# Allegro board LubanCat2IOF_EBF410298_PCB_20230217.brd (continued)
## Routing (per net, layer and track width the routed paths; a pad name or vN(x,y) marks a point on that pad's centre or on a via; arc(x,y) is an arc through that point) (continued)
MIPI_DSI_TX0_D3N: length 111.2
  TOP w0.114: J38.224 72.35,71.42 arc(72.36,71.49) 72.41,71.56 72.42,71.57 arc(72.46,71.64) 72.48,71.71 72.48,74.75 arc(72.67,75.21) 73.13,75.4 96.93,75.4 v1(97.26,75.73) ; J23.30 152.2,78.93 arc(152.27,78.91) 152.34,78.87 152.35,78.85 arc(152.42,78.81) 152.49,78.8 155.18,78.8 arc(155.39,78.84) 155.56,78.95 v1(155.73,79.12)
  ART03 w0.102: v1(97.26,75.73) 97.1,75.57 arc(96.94,75.46) 96.74,75.42 arc(96.35,75.26) 96.18,74.86 96.18,74.71 arc(96.38,74.23) 96.85,74.04 98.01,74.04 arc(98.21,74.08) 98.37,74.19 99.3,75.12 arc(99.46,75.22) 99.64,75.26 arc(100.99,75.53) 102.14,76.29 102.95,77.1 arc(103.27,77.32) 103.64,77.39 146.07,77.39 arc(146.5,77.3) 146.86,77.06 arc(146.94,76.95) 146.96,76.81 146.96,72.71 arc(147,72.52) 147.11,72.35 147.13,72.33 arc(147.3,72.22) 147.49,72.18 150.75,72.18 arc(150.83,72.17) 150.9,72.12 151.75,71.27 arc(151.92,71.15) 152.11,71.12 155.88,71.12 arc(156.49,71.37) 156.74,71.98 156.74,78.31 arc(156.6,78.67) 156.24,78.81 arc(156.05,78.85) 155.89,78.96 v1(155.73,79.12)
MIPI_DSI_TX0_D3P: length 111.2
  TOP w0.114: J38.226 72.85,71.5 72.72,71.63 72.72,74.75 arc(72.84,75.04) 73.13,75.16 73.98,75.16 arc(74.1,75.11) 74.15,74.99 arc(74.19,74.87) 74.31,74.82 74.43,74.82 arc(74.55,74.87) 74.6,74.99 arc(74.65,75.11) 74.77,75.16 74.89,75.16 arc(75.01,75.11) 75.06,74.99 arc(75.11,74.87) 75.23,74.82 75.35,74.82 arc(75.47,74.87) 75.52,74.99 arc(75.57,75.11) 75.69,75.16 75.81,75.16 arc(75.93,75.11) 75.97,74.99 arc(76.04,74.84) 76.19,74.77 76.21,74.77 arc(76.37,74.84) 76.43,74.99 arc(76.48,75.11) 76.6,75.16 77.74,75.16 arc(77.87,75.1) 77.93,74.97 arc(77.99,74.83) 78.12,74.77 78.19,74.77 arc(78.33,74.83) 78.39,74.97 arc(78.44,75.1) 78.58,75.16 78.65,75.16 arc(78.79,75.1) 78.84,74.97 arc(78.9,74.83) 79.04,74.77 79.11,74.77 arc(79.24,74.83) 79.3,74.97 arc(79.36,75.1) 79.5,75.16 96.93,75.16 v1(97.26,74.84) ; J23.29 152.28,78.42 152.35,78.5 arc(152.42,78.54) 152.49,78.55 155.18,78.55 arc(155.39,78.51) 155.56,78.4 v1(155.73,78.23)
  ART03 w0.102: v1(155.73,78.23) 155.89,78.39 arc(156.05,78.5) 156.24,78.54 156.24,78.54 arc(156.4,78.47) 156.46,78.31 156.46,71.98 arc(156.29,71.57) 155.88,71.4 152.11,71.4 arc(152.03,71.41) 151.95,71.46 151.09,72.32 arc(150.94,72.43) 150.75,72.46 147.49,72.46 arc(147.4,72.48) 147.33,72.53 147.31,72.55 arc(147.26,72.62) 147.24,72.71 147.24,76.81 arc(147.2,77.05) 147.06,77.26 arc(146.6,77.56) 146.07,77.67 103.64,77.67 arc(103.16,77.57) 102.76,77.3 101.95,76.49 arc(100.89,75.78) 99.64,75.54 arc(99.35,75.48) 99.1,75.31 98.17,74.38 arc(98.1,74.33) 98.01,74.32 96.85,74.32 arc(96.58,74.43) 96.46,74.71 96.46,74.86 arc(96.54,75.06) 96.74,75.14 arc(96.94,75.1) 97.1,75 v1(97.26,74.84)
MIPI_DSI_TX1_CLKN: length 96.1
  TOP w0.114: J38.207 67.6,61.38 arc(67.61,61.31) 67.66,61.24 67.67,61.23 arc(67.71,61.16) 67.73,61.09 67.73,60.62 arc(67.88,59.88) 68.3,59.24 71.49,56.06 arc(71.9,55.78) 72.38,55.69 75.6,55.69 arc(75.8,55.65) 75.97,55.53 v1(76.14,55.36) ; v1(118.57,56.53) 118.74,56.36 arc(118.91,56.25) 119.11,56.21 129.08,56.21 arc(130.26,55.97) 131.25,55.31 132.87,53.69 arc(133.56,53.23) 134.38,53.06 150.47,53.06 arc(150.54,53.08) 150.61,53.12 150.62,53.14 arc(150.69,53.18) 150.76,53.19 J26.24
  BOTTOM w0.114: v1(76.14,55.36) 76.3,55.52 arc(76.46,55.62) 76.64,55.66 77.97,55.66 arc(78.19,55.7) 78.37,55.83 79.07,56.53 arc(80.24,57.31) 81.63,57.59 85.85,57.59 arc(86.22,57.74) 86.38,58.11 86.38,58.52 arc(86.66,58.81) 86.95,58.52 86.95,58.11 arc(87.1,57.74) 87.48,57.59 119.85,57.59 arc(120.01,57.52) 120.08,57.36 120.08,56.43 arc(120.01,56.27) 119.85,56.21 119.11,56.21 arc(118.91,56.25) 118.74,56.36 v1(118.57,56.53)
MIPI_DSI_TX1_CLKP: length 96.5
  TOP w0.114: v1(76.14,56.25) 75.97,56.08 arc(75.8,55.97) 75.6,55.93 72.38,55.93 arc(71.99,56.01) 71.66,56.23 68.47,59.41 arc(68.1,59.97) 67.97,60.62 67.97,61.09 arc(67.99,61.16) 68.03,61.23 68.04,61.24 arc(68.09,61.31) 68.1,61.38 J38.209 ; J26.23 150.76,52.69 arc(150.69,52.71) 150.62,52.75 150.61,52.76 arc(150.54,52.81) 150.47,52.82 134.38,52.82 arc(133.47,53) 132.7,53.52 131.08,55.14 arc(130.16,55.75) 129.08,55.97 119.11,55.97 arc(118.91,55.92) 118.74,55.81 v1(118.57,55.64)
  BOTTOM w0.114: v1(76.14,56.25) 76.33,56.07 arc(76.51,55.95) 76.73,55.9 77.97,55.9 arc(78.09,55.93) 78.2,56 78.9,56.7 arc(80.15,57.53) 81.63,57.83 85.85,57.83 arc(86.05,57.91) 86.14,58.11 86.14,58.52 arc(86.66,59.05) 87.19,58.52 87.19,58.11 arc(87.27,57.91) 87.48,57.83 119.85,57.83 arc(120.18,57.69) 120.32,57.36 120.32,56.43 arc(120.18,56.1) 119.85,55.97 119.11,55.97 arc(118.91,55.92) 118.74,55.81 v1(118.57,55.64)
MIPI_DSI_TX1_D0N: length 96.8
  TOP w0.114: v1(114.22,54.35) 114.39,54.52 arc(114.5,54.69) 114.54,54.9 114.54,54.93 arc(114.74,55.92) 115.3,56.76 arc(116.37,57.48) 117.65,57.73 129.29,57.73 arc(130.69,57.45) 131.87,56.66 132.84,55.69 arc(134.09,54.86) 135.57,54.56 150.47,54.56 arc(150.54,54.58) 150.61,54.62 150.62,54.64 arc(150.69,54.68) 150.76,54.69 J26.27 ; v1(76.14,52.79) 75.97,52.96 arc(75.8,53.07) 75.6,53.11 73.9,53.11 arc(71.97,53.5) 70.34,54.59 65.9,59.02 arc(65.4,59.77) 65.23,60.65 65.23,61.09 arc(65.21,61.16) 65.17,61.23 65.16,61.24 arc(65.11,61.31) 65.1,61.38 J38.197
  BOTTOM w0.114: v1(114.22,54.35) 114.39,54.52 arc(114.5,54.69) 114.54,54.9 arc(114.34,55.39) 113.84,55.6 81.95,55.6 arc(81.01,55.41) 80.22,54.88 78.83,53.49 arc(78.31,53.14) 77.69,53.02 76.52,53.02 arc(76.38,52.99) 76.27,52.91 v1(76.14,52.79)
MIPI_DSI_TX1_D0P: length 97.5
  TOP w0.114: v1(76.14,53.68) 75.97,53.51 arc(75.8,53.4) 75.6,53.36 73.9,53.36 arc(72.06,53.72) 70.51,54.76 66.07,59.2 arc(65.63,59.86) 65.47,60.65 65.47,61.09 arc(65.49,61.16) 65.53,61.23 65.54,61.24 arc(65.59,61.31) 65.6,61.38 J38.199 ; J26.26 150.76,54.19 arc(150.69,54.21) 150.62,54.25 150.61,54.26 arc(150.54,54.31) 150.47,54.32 150.17,54.32 arc(150.09,54.29) 150.06,54.21 arc(150.03,54.13) 149.95,54.1 149.72,54.1 arc(149.64,54.13) 149.6,54.21 arc(149.57,54.29) 149.49,54.32 149.25,54.32 arc(149.19,54.3) 149.17,54.24 arc(149.14,54.18) 149.09,54.16 148.68,54.16 arc(148.62,54.18) 148.6,54.24 arc(148.57,54.3) 148.51,54.32 148.11,54.32 arc(148.05,54.3) 148.03,54.24 arc(148,54.18) 147.94,54.16 147.54,54.16 arc(147.48,54.18) 147.45,54.24 arc(147.43,54.3) 147.37,54.32 146.96,54.32 arc(146.91,54.3) 146.88,54.24 arc(146.86,54.18) 146.8,54.16 146.39,54.16 arc(146.33,54.18) 146.31,54.24 arc(146.29,54.3) 146.23,54.32 145.82,54.32 arc(145.76,54.3) 145.74,54.24 arc(145.71,54.18) 145.66,54.16 145.25,54.16 arc(145.19,54.18) 145.17,54.24 arc(145.14,54.3) 145.08,54.32 135.57,54.32 arc(134,54.63) 132.67,55.52 131.7,56.49 arc(130.59,57.23) 129.29,57.49 117.65,57.49 arc(116.47,57.25) 115.47,56.59 arc(114.96,55.83) 114.78,54.93 114.78,54.9 arc(114.82,54.69) 114.94,54.52 v1(115.11,54.35)
  BOTTOM w0.114: v1(76.14,53.68) 76.4,53.43 arc(76.58,53.3) 76.8,53.26 77.69,53.26 arc(78.21,53.36) 78.66,53.66 80.04,55.05 arc(80.92,55.63) 81.95,55.84 113.84,55.84 arc(114.51,55.56) 114.78,54.9 arc(114.82,54.69) 114.94,54.52 v1(115.11,54.35)
MIPI_DSI_TX1_D1N: length 96.1
  TOP w0.114: v1(74.52,54.09) 74.35,54.26 arc(74.18,54.38) 73.97,54.42 72.5,54.42 arc(71.79,54.56) 71.19,54.96 66.61,59.54 arc(66.33,59.96) 66.23,60.46 66.23,61.09 arc(66.21,61.16) 66.17,61.23 66.16,61.24 arc(66.11,61.31) 66.1,61.38 J38.201 ; J26.21 150.76,51.69 arc(150.69,51.68) 150.62,51.64 150.61,51.62 arc(150.54,51.58) 150.47,51.56 149.83,51.56 arc(149.76,51.59) 149.73,51.66 arc(149.7,51.73) 149.63,51.76 149.26,51.76 arc(149.19,51.73) 149.16,51.66 arc(149.13,51.59) 149.06,51.56 148.69,51.56 arc(148.62,51.59) 148.59,51.66 arc(148.56,51.73) 148.49,51.76 148.12,51.76 arc(148.05,51.73) 148.02,51.66 arc(147.99,51.59) 147.92,51.56 133.51,51.56 arc(132.92,51.68) 132.43,52.01 129.97,54.47 arc(129.48,54.79) 128.91,54.91 116.77,54.91 arc(116.57,54.95) 116.4,55.06 v1(116.23,55.23)
  BOTTOM w0.114: v1(74.52,54.09) 74.66,54.23 arc(74.79,54.32) 74.95,54.35 78.09,54.35 arc(78.31,54.4) 78.49,54.52 79.66,55.69 arc(80.63,56.33) 81.77,56.56 116.83,56.56 arc(117.02,56.48) 117.11,56.28 117.11,55.11 arc(117.05,54.97) 116.9,54.91 116.77,54.91 arc(116.57,54.95) 116.4,55.06 v1(116.23,55.23)
MIPI_DSI_TX1_D1P: length 96.1
  TOP w0.114: v1(116.23,54.34) 116.4,54.51 arc(116.57,54.63) 116.77,54.67 128.91,54.67 arc(129.39,54.57) 129.8,54.3 132.26,51.84 arc(132.83,51.46) 133.51,51.32 150.47,51.32 arc(150.54,51.31) 150.61,51.26 150.62,51.25 arc(150.69,51.21) 150.76,51.19 J26.20 ; v1(74.52,54.98) 74.35,54.81 arc(74.18,54.7) 73.97,54.66 72.5,54.66 arc(71.88,54.78) 71.36,55.13 66.78,59.71 arc(66.55,60.05) 66.47,60.46 66.47,61.09 arc(66.49,61.16) 66.53,61.23 66.54,61.24 arc(66.59,61.31) 66.6,61.38 J38.203
  BOTTOM w0.114: v1(116.23,54.34) 116.4,54.51 arc(116.57,54.63) 116.77,54.67 116.9,54.67 arc(117.22,54.8) 117.35,55.11 117.35,56.28 arc(117.2,56.65) 116.83,56.8 81.77,56.8 arc(80.54,56.56) 79.49,55.86 78.32,54.69 arc(78.22,54.62) 78.09,54.59 75.14,54.59 arc(74.92,54.64) 74.74,54.76 v1(74.52,54.98)
MIPI_DSI_TX1_D2N: length 96.7
  TOP w0.114: v1(74.52,56.5) 74.29,56.73 arc(74.11,56.86) 73.89,56.9 72.63,56.9 arc(72.12,57) 71.69,57.29 69.69,59.29 arc(69.35,59.8) 69.23,60.39 69.23,61.09 arc(69.21,61.16) 69.17,61.23 69.16,61.24 arc(69.11,61.31) 69.1,61.38 J38.213 ; J26.18 150.76,50.19 arc(150.69,50.18) 150.62,50.14 150.61,50.12 arc(150.54,50.08) 150.47,50.06 150.23,50.06 arc(150.18,50.08) 150.17,50.12 arc(150.15,50.17) 150.1,50.19 149.77,50.19 arc(149.73,50.17) 149.71,50.12 arc(149.69,50.08) 149.65,50.06 133.53,50.06 arc(132.35,50.3) 131.35,50.96 129.42,52.89 arc(128.65,53.41) 127.74,53.59 120.41,53.59 arc(120.2,53.63) 120.03,53.74 v1(119.86,53.92)
  BOTTOM w0.114: v1(119.86,53.92) 120.08,53.7 arc(120.2,53.62) 120.34,53.59 120.49,53.59 arc(120.83,53.73) 120.97,54.07 120.97,57.64 arc(120.68,58.32) 120,58.61 89.28,58.61 arc(88.88,58.77) 88.71,59.18 88.71,59.56 arc(88.64,59.72) 88.48,59.79 85.81,59.79 arc(85.65,59.72) 85.59,59.56 85.59,59.22 arc(85.54,59) 85.41,58.8 arc(85.19,58.66) 84.94,58.61 81.71,58.61 arc(79.74,58.21) 78.07,57.1 arc(77.88,56.97) 77.66,56.93 75.18,56.93 arc(74.96,56.89) 74.78,56.76 v1(74.52,56.5)
MIPI_DSI_TX1_D2P: length 96.8
  TOP w0.114: v1(74.52,57.39) 74.38,57.26 arc(74.25,57.17) 74.09,57.14 72.63,57.14 arc(72.21,57.22) 71.86,57.46 69.86,59.46 arc(69.57,59.89) 69.47,60.39 69.47,61.09 arc(69.49,61.16) 69.53,61.23 69.54,61.24 arc(69.59,61.31) 69.6,61.38 J38.215 ; v1(119.86,53.02) 120.03,53.19 arc(120.2,53.31) 120.41,53.35 127.74,53.35 arc(128.56,53.19) 129.25,52.72 131.18,50.79 arc(132.26,50.07) 133.53,49.82 150.47,49.82 arc(150.54,49.81) 150.61,49.76 150.62,49.75 arc(150.69,49.71) 150.76,49.69 J26.17
  BOTTOM w0.114: v1(119.86,53.02) 120.05,53.21 arc(120.2,53.31) 120.39,53.35 120.49,53.35 arc(121,53.56) 121.21,54.07 121.21,57.64 arc(120.85,58.49) 120,58.85 89.28,58.85 arc(89.05,58.94) 88.95,59.18 88.95,59.56 arc(88.81,59.89) 88.48,60.03 85.81,60.03 arc(85.48,59.89) 85.34,59.56 85.34,59.22 arc(85.32,59.09) 85.24,58.97 arc(85.1,58.88) 84.94,58.85 81.71,58.85 arc(79.65,58.44) 77.9,57.27 arc(77.79,57.2) 77.66,57.17 74.89,57.17 arc(74.75,57.2) 74.64,57.28 v1(74.52,57.39)
MIPI_DSI_TX1_D3N: length 95.8
  TOP w0.114: v1(76.14,57.77) 75.86,58.06 arc(75.67,58.18) 75.45,58.23 72.78,58.23 arc(72.05,58.37) 71.43,58.78 70.58,59.63 arc(70.32,60.02) 70.23,60.48 70.23,61.09 arc(70.21,61.16) 70.17,61.23 70.16,61.24 arc(70.11,61.31) 70.1,61.38 J38.217 ; J26.30 150.76,56.19 arc(150.69,56.18) 150.62,56.14 150.61,56.12 arc(150.54,56.08) 150.47,56.06 135.29,56.06 arc(134.31,56.26) 133.48,56.81 132.72,57.58 arc(131.23,58.57) 129.47,58.92 118.47,58.92 arc(118.38,58.94) 118.31,58.99 117.66,59.64 arc(117.61,59.71) 117.6,59.8 117.6,60.2 arc(117.66,60.54) 117.85,60.82 v1(117.86,60.83)
  BOTTOM w0.114: v1(76.14,57.77) 76.32,57.95 arc(76.51,58.08) 76.72,58.12 77.27,58.12 arc(77.48,58.16) 77.67,58.29 arc(79.12,59.25) 80.82,59.59 82.09,59.59 arc(82.47,59.75) 82.62,60.12 82.62,60.36 arc(82.7,60.56) 82.9,60.64 82.91,60.64 arc(83.11,60.55) 83.19,60.35 83.19,60.12 arc(83.35,59.75) 83.72,59.59 83.96,59.59 arc(84.14,59.63) 84.29,59.73 arc(84.42,59.92) 84.47,60.15 84.47,61.48 arc(84.53,61.63) 84.68,61.69 84.92,61.69 arc(85.13,61.61) 85.21,61.41 85.21,61.28 arc(85.37,60.91) 85.74,60.75 85.79,60.75 arc(86.13,60.89) 86.26,61.22 86.26,61.41 arc(86.55,61.69) 86.84,61.41 86.84,61.28 arc(86.99,60.91) 87.36,60.75 87.42,60.75 arc(87.75,60.89) 87.89,61.22 87.89,61.41 arc(87.97,61.61) 88.18,61.69 89.55,61.69 arc(89.71,61.63) 89.78,61.46 89.78,60.08 arc(89.92,59.73) 90.26,59.59 116.88,59.59 arc(117.1,59.63) 117.29,59.76 117.44,59.91 arc(117.56,60.09) 117.6,60.29 arc(117.65,60.54) 117.79,60.76 v1(117.86,60.83)
MIPI_DSI_TX1_D3P: length 96
  TOP w0.114: J38.219 70.6,61.38 arc(70.59,61.31) 70.54,61.24 70.53,61.23 arc(70.49,61.16) 70.47,61.09 70.47,60.48 arc(70.54,60.11) 70.75,59.8 71.6,58.96 arc(72.14,58.59) 72.78,58.47 75.82,58.47 arc(75.94,58.49) 76.04,58.56 v1(76.14,58.66) ; J26.29 150.76,55.69 arc(150.69,55.71) 150.62,55.75 150.61,55.76 arc(150.54,55.81) 150.47,55.82 150.16,55.82 arc(150.08,55.79) 150.05,55.71 arc(150.01,55.63) 149.93,55.6 149.7,55.6 arc(149.62,55.63) 149.59,55.71 arc(149.55,55.79) 149.48,55.82 149.23,55.82 arc(149.15,55.79) 149.12,55.71 arc(149.09,55.63) 149.01,55.6 148.66,55.6 arc(148.58,55.63) 148.55,55.71 arc(148.52,55.79) 148.44,55.82 135.29,55.82 arc(134.22,56.03) 133.31,56.64 132.55,57.41 arc(131.14,58.35) 129.47,58.68 118.47,58.68 arc(118.29,58.72) 118.14,58.82 117.49,59.47 arc(117.39,59.62) 117.35,59.8 117.35,60.2 arc(117.31,60.42) 117.19,60.61 v1(116.97,60.83)
  BOTTOM w0.114: v1(116.97,60.83) 117.27,60.53 arc(117.33,60.43) 117.35,60.32 117.35,60.29 arc(117.33,60.18) 117.27,60.08 117.11,59.93 arc(117.01,59.86) 116.88,59.83 90.26,59.83 arc(90.09,59.9) 90.02,60.08 90.02,61.46 arc(89.88,61.8) 89.55,61.93 88.18,61.93 arc(87.8,61.78) 87.65,61.41 87.65,61.22 arc(87.58,61.06) 87.42,60.99 87.36,60.99 arc(87.16,61.08) 87.08,61.28 87.08,61.41 arc(86.55,61.93) 86.02,61.41 86.02,61.22 arc(85.96,61.06) 85.79,60.99 85.74,60.99 arc(85.54,61.08) 85.45,61.28 85.45,61.41 arc(85.3,61.78) 84.92,61.93 84.68,61.93 arc(84.36,61.8) 84.23,61.48 84.23,60.15 arc(84.2,60.01) 84.12,59.9 arc(84.05,59.85) 83.96,59.83 83.72,59.83 arc(83.52,59.92) 83.43,60.12 83.43,60.35 arc(83.28,60.73) 82.91,60.88 82.9,60.88 arc(82.53,60.73) 82.38,60.36 82.38,60.12 arc(82.3,59.92) 82.09,59.83 80.82,59.83 arc(79.02,59.47) 77.5,58.46 arc(77.39,58.38) 77.27,58.36 76.65,58.36 arc(76.47,58.4) 76.3,58.5 v1(76.14,58.66)
OE: length 5
  TOP w0.173: R83.2 142.43,71.67 142.61,71.85 142.61,74.45 142.43,74.62 U21.8
ON/OFF_KEY: length 63.3
  TOP w0.173: J38.33 22.6,37.97 21.08,36.45 21.08,30.98 23.89,28.17 23.89,13.29 23.47,12.87 17.02,12.87 v1(16.51,13.38)
  BOTTOM w0.173: v1(16.51,13.38) C64.1 15.61,12.54 D2.2 16.45,11.7 SW2.2
PCIE20_CLKREQN_M1: length 82.5
  TOP w0.173: J38.231 73.6,60.41 v1(74.1,59.91)
  ART03 w0.16: v1(74.1,59.91) 74.1,58.87 76.11,56.86 105.56,56.86 105.88,56.54 v1(105.88,52.65)
  ART04 w0.16: v1(125.48,72.57) 123.77,70.87 123.77,51.15 123.06,50.44 v1(121.03,50.44)
  BOTTOM w0.173: R30.1 v1(125.48,72.57) ; v1(121.03,50.44) 113.13,50.44 110.92,52.65 v1(105.88,52.65)
PCIE20_PERSTN_M1: length 43.1
  TOP w0.173: J38.247 v1(77.6,63.93) ; R63.2 v1(116.97,63.83)
  BOTTOM w0.173: v1(77.6,63.93) 79.23,65.55 97.41,65.55 97.84,65.12 102.21,65.12 102.84,64.49 116.31,64.49 v1(116.97,63.83)
PCIE20_REFCLKN: length 89.4
  TOP w0.152: J38.140 49.35,69.23 arc(49.36,69.16) 49.4,69.11 49.42,69.09 arc(49.46,69.03) 49.47,68.97 49.47,67.51 arc(50.07,66.05) 51.53,65.45 56.39,65.45 arc(56.58,65.41) 56.74,65.3 57.03,65.01 arc(57.28,64.84) 57.57,64.79 93.69,64.79 arc(94.28,64.67) 94.78,64.33 96.34,62.77 arc(96.53,62.65) 96.74,62.61 100.34,62.61 arc(102.22,63.38) 103,65.26 103,67 arc(103.25,68.27) 103.97,69.34 104.37,69.74 arc(104.62,69.91) 104.92,69.97 106.08,69.97 arc(106.54,70.07) 106.93,70.33 106.95,70.34 arc(108.14,71.14) 109.55,71.42 121.2,71.42 arc(123.48,72.37) 124.43,74.65 124.43,74.98 arc(124.46,75.15) 124.55,75.28 124.58,75.31 arc(124.67,75.44) 124.7,75.61 J35.11
PCIE20_REFCLKP: length 89.3
  TOP w0.152: J38.142 49.85,69.23 arc(49.84,69.16) 49.8,69.11 49.78,69.09 arc(49.74,69.03) 49.73,68.97 49.73,67.51 arc(50.26,66.23) 51.53,65.71 56.39,65.71 arc(56.68,65.65) 56.93,65.48 57.22,65.19 arc(57.38,65.08) 57.57,65.05 93.69,65.05 arc(94.38,64.91) 94.97,64.52 96.53,62.96 arc(96.63,62.89) 96.74,62.87 97.03,62.87 arc(97.15,62.91) 97.2,63.03 arc(97.24,63.14) 97.36,63.19 97.64,63.19 arc(97.76,63.14) 97.81,63.03 arc(97.85,62.91) 97.97,62.87 98.25,62.87 arc(98.37,62.91) 98.42,63.03 arc(98.46,63.14) 98.58,63.19 98.86,63.19 arc(98.98,63.14) 99.03,63.03 arc(99.07,62.91) 99.19,62.87 100.34,62.87 arc(102.04,63.57) 102.74,65.26 102.74,67 arc(103.01,68.37) 103.79,69.53 104.18,69.93 arc(104.52,70.15) 104.92,70.23 106.08,70.23 arc(106.44,70.3) 106.75,70.51 106.77,70.53 arc(108.04,71.38) 109.55,71.68 121.2,71.68 arc(123.3,72.55) 124.17,74.65 124.17,74.98 arc(124.14,75.15) 124.05,75.28 124.02,75.31 arc(123.93,75.44) 123.9,75.61 J35.13
PCIE20_RXN: length 89.3
  TOP w0.152: J38.150 51.85,69.23 arc(51.86,69.17) 51.9,69.11 51.92,69.09 arc(51.96,69.03) 51.97,68.97 51.97,68.22 arc(52.34,67.34) 53.22,66.97 57.35,66.97 arc(57.55,66.93) 57.71,66.82 57.99,66.54 arc(58.24,66.37) 58.53,66.32 63.47,66.32 arc(63.87,66.48) 64.03,66.88 64.03,67.89 arc(64.12,68.11) 64.34,68.2 72.43,68.2 arc(72.64,68.11) 72.73,67.89 72.73,66.88 arc(72.9,66.48) 73.3,66.32 90.74,66.32 arc(92.29,66.62) 93.6,67.5 96.14,70.04 arc(97.16,70.72) 98.36,70.96 104.44,70.96 arc(104.96,71.06) 105.39,71.35 106,71.96 arc(106.44,72.26) 106.97,72.36 117.35,72.36 arc(117.75,72.53) 117.91,72.92 117.91,73.11 arc(117.98,73.28) 118.15,73.35 118.22,73.35 arc(118.43,73.26) 118.52,73.04 118.52,72.92 arc(119.09,72.36) 119.65,72.92 119.65,73.11 arc(119.72,73.28) 119.88,73.35 119.95,73.35 arc(120.17,73.26) 120.26,73.04 120.26,72.92 arc(120.42,72.53) 120.82,72.36 121.1,72.36 arc(121.52,72.53) 121.69,72.95 121.69,73.99 arc(121.51,74.44) 121.06,74.62 116.79,74.62 arc(116.54,74.73) 116.43,74.98 arc(116.46,75.15) 116.55,75.28 116.58,75.31 arc(116.67,75.44) 116.7,75.61 J35.23
PCIE20_RXP: length 89.4
  TOP w0.152: J35.25 115.9,75.61 arc(115.93,75.44) 116.02,75.31 116.05,75.28 arc(116.14,75.15) 116.17,74.98 arc(116.35,74.54) 116.79,74.36 121.06,74.36 arc(121.32,74.25) 121.43,73.99 121.43,72.95 arc(121.34,72.72) 121.1,72.62 120.82,72.62 arc(120.61,72.71) 120.52,72.92 120.52,73.04 arc(120.35,73.44) 119.95,73.61 119.88,73.61 arc(119.53,73.46) 119.39,73.11 119.39,72.92 arc(119.09,72.62) 118.78,72.92 118.78,73.04 arc(118.62,73.44) 118.22,73.61 118.15,73.61 arc(117.8,73.46) 117.65,73.11 117.65,72.92 arc(117.56,72.71) 117.35,72.62 106.97,72.62 arc(106.34,72.5) 105.82,72.14 105.21,71.54 arc(104.86,71.3) 104.44,71.22 98.36,71.22 arc(97.06,70.96) 95.96,70.22 93.42,67.68 arc(92.19,66.86) 90.74,66.57 73.3,66.57 arc(73.08,66.66) 72.99,66.88 72.99,67.89 arc(72.83,68.29) 72.43,68.45 64.34,68.45 arc(63.94,68.29) 63.77,67.89 63.77,66.88 arc(63.68,66.66) 63.47,66.57 62.92,66.57 arc(62.78,66.63) 62.72,66.78 arc(62.66,66.92) 62.52,66.98 62.31,66.98 arc(62.17,66.92) 62.11,66.78 arc(62.05,66.63) 61.91,66.57 61.7,66.57 arc(61.56,66.63) 61.5,66.78 arc(61.44,66.92) 61.3,66.98 61.09,66.98 arc(60.95,66.92) 60.89,66.78 arc(60.83,66.63) 60.69,66.57 58.53,66.57 arc(58.34,66.61) 58.18,66.72 57.89,67.01 arc(57.64,67.17) 57.35,67.23 53.22,67.23 arc(52.52,67.52) 52.23,68.22 52.23,69.04 52.35,69.16 J38.152
PCIE20_TXN: length 85.1
  TOP w0.152: v1(101.54,68.47) 101.37,68.31 arc(101.26,68.15) 101.22,67.96 101.22,65.41 arc(101.17,65.12) 101,64.87 100.41,64.28 arc(100.16,64.11) 99.87,64.05 96.73,64.05 arc(96.29,64.14) 95.92,64.39 95.53,64.78 arc(94.68,65.35) 93.69,65.54 72.16,65.54 arc(71.76,65.71) 71.6,66.11 71.6,67.07 arc(71.29,67.38) 70.99,67.07 70.99,66.11 arc(70.42,65.54) 69.86,66.11 69.86,67.07 arc(69.55,67.38) 69.25,67.07 69.25,66.11 arc(68.68,65.54) 68.12,66.11 68.12,67.07 arc(67.82,67.38) 67.51,67.07 67.51,66.11 arc(66.95,65.54) 66.38,66.11 66.38,67.07 arc(66.08,67.38) 65.77,67.07 65.77,66.11 arc(65.61,65.71) 65.21,65.54 57.95,65.54 arc(57.66,65.6) 57.41,65.77 57.05,66.12 arc(56.95,66.19) 56.84,66.21 52.02,66.21 arc(51.73,66.27) 51.48,66.44 51.19,66.72 arc(51.03,66.97) 50.97,67.26 50.97,68.97 arc(50.96,69.03) 50.92,69.09 50.9,69.11 arc(50.86,69.17) 50.85,69.23 J38.146
  BOTTOM w0.152: C53.1 113.59,71.13 arc(113.54,71.02) 113.44,70.98 113.36,70.98 arc(113.25,70.93) 113.21,70.82 113.21,69.94 arc(113.18,69.78) 113.09,69.65 113.05,69.61 arc(112.77,69.42) 112.44,69.36 101.53,69.36 arc(101.32,69.27) 101.23,69.05 101.23,68.98 arc(101.27,68.8) 101.37,68.64 v1(101.54,68.47)
PCIE20_TXP: length 85.2
  TOP w0.152: v1(100.65,68.47) 100.82,68.31 arc(100.93,68.15) 100.97,67.96 100.97,67.51 arc(100.9,67.36) 100.75,67.3 arc(100.6,67.23) 100.53,67.08 100.53,66.9 arc(100.6,66.75) 100.75,66.69 arc(100.9,66.62) 100.97,66.47 100.97,65.41 arc(100.93,65.22) 100.82,65.06 100.22,64.46 arc(100.06,64.35) 99.87,64.31 96.73,64.31 arc(96.39,64.38) 96.1,64.57 95.71,64.97 arc(94.78,65.59) 93.69,65.8 72.16,65.8 arc(71.94,65.89) 71.85,66.11 71.85,67.07 arc(71.29,67.64) 70.73,67.07 70.73,66.11 arc(70.42,65.8) 70.12,66.11 70.12,67.07 arc(69.55,67.64) 68.99,67.07 68.99,66.11 arc(68.68,65.8) 68.38,66.11 68.38,67.07 arc(67.82,67.64) 67.25,67.07 67.25,66.11 arc(66.95,65.8) 66.64,66.11 66.64,67.07 arc(66.08,67.64) 65.52,67.07 65.52,66.11 arc(65.43,65.89) 65.21,65.8 57.95,65.8 arc(57.76,65.84) 57.59,65.95 57.23,66.31 arc(57.05,66.43) 56.84,66.47 52.02,66.47 arc(51.83,66.51) 51.66,66.62 51.38,66.91 arc(51.27,67.07) 51.23,67.26 51.23,68.97 arc(51.24,69.03) 51.28,69.09 51.3,69.11 arc(51.34,69.17) 51.35,69.23 J38.148
  BOTTOM w0.152: C54.1 112.57,71.13 arc(112.62,71.02) 112.73,70.98 112.8,70.98 arc(112.91,70.93) 112.95,70.82 112.95,69.94 arc(112.94,69.88) 112.91,69.83 112.87,69.8 arc(112.67,69.66) 112.44,69.62 112.01,69.62 arc(111.89,69.67) 111.84,69.78 arc(111.79,69.9) 111.68,69.95 111.4,69.95 arc(111.28,69.9) 111.23,69.78 arc(111.18,69.67) 111.07,69.62 101.53,69.62 arc(101.14,69.45) 100.97,69.05 100.97,69 arc(100.93,68.81) 100.82,68.64 v1(100.65,68.47)
PCIE20_WAKEN_M1: length 88.8
  TOP w0.173: J38.227 72.6,60.41 v1(73.1,59.91)
  ART03 w0.16: v1(73.1,59.91) 73.59,59.41 73.59,56.32 74.17,55.75 74.8,55.75 76,54.56 77.93,54.56 79.71,56.33 104.56,56.33 104.88,56.01 v1(104.88,52.65)
  ART04 w0.16: v1(125.48,71.57) 124.81,70.91 124.81,49.73 124.27,49.19 v1(121.03,49.19)
  BOTTOM w0.173: R29.1 126.74,71.93 125.83,71.93 v1(125.48,71.57) ; v1(121.03,49.19) 120.41,49.81 113.03,49.81 110.71,52.13 105.4,52.13 v1(104.88,52.65)
PCIE30_REFCLKN_IN: length 182.6
  TOP w0.114: J38.139 49.1,61.35 arc(49.09,61.3) 49.07,61.27 49,61.2 arc(48.98,61.17) 48.97,61.12 48.97,60.66 arc(49,60.6) 49.06,60.57 arc(49.12,60.55) 49.15,60.48 49.15,60.2 arc(49.12,60.14) 49.06,60.11 arc(49,60.09) 48.97,60.03 48.97,59.75 arc(49,59.68) 49.06,59.66 arc(49.12,59.63) 49.15,59.57 49.15,59.29 arc(49.12,59.23) 49.06,59.2 arc(49,59.17) 48.97,59.11 48.97,39.65 arc(49.4,37.49) 50.62,35.66 53.92,32.36 arc(56.06,30.93) 58.6,30.43 139.51,30.43 arc(140.01,30.63) 140.22,31.14 140.22,35.09 arc(140.38,35.47) 140.76,35.63 140.87,35.63 arc(140.91,35.63) 140.95,35.66 v1(141.22,35.93) ; v1(145.1,83.3) 145.39,83.02 arc(145.41,82.98) 145.42,82.94 145.42,82.61 arc(145.39,82.53) 145.31,82.49 145.15,82.49 arc(145.07,82.46) 145.03,82.38 R78.2
  ART04 w0.102: v1(145.1,83.3) 145.37,83.03 arc(145.39,83) 145.4,82.96 145.4,80.36 arc(145.66,79.05) 146.41,77.93 arc(146.99,77.06) 147.19,76.04 147.19,36.17 arc(147.15,35.94) 147.02,35.75 arc(146.9,35.67) 146.76,35.65 141.55,35.65 arc(141.51,35.65) 141.48,35.67 v1(141.22,35.93)
  BOTTOM w0.114: R78.2 145.03,82.38 arc(145.07,82.46) 145.15,82.49 145.31,82.49 arc(145.39,82.53) 145.42,82.61 145.42,82.94 arc(145.41,82.98) 145.39,83.02 v1(145.1,83.3)
PCIE30_REFCLKP_IN: length 183
  TOP w0.114: J38.137 48.6,61.35 arc(48.61,61.3) 48.63,61.27 48.7,61.2 arc(48.72,61.17) 48.73,61.12 48.73,39.65 arc(49.18,37.39) 50.45,35.49 53.74,32.19 arc(55.97,30.71) 58.6,30.18 139.51,30.18 arc(140.18,30.46) 140.46,31.14 140.46,35.09 arc(140.55,35.3) 140.76,35.38 140.87,35.38 arc(140.91,35.38) 140.95,35.35 v1(141.22,35.08) ; v1(145.98,83.3) 145.7,83.02 arc(145.67,82.98) 145.66,82.94 145.66,82.61 arc(145.7,82.53) 145.78,82.49 145.94,82.49 arc(146.02,82.46) 146.05,82.38 R77.2
  ART04 w0.102: v1(141.22,35.08) 141.48,35.34 arc(141.51,35.36) 141.55,35.37 146.76,35.37 arc(147.01,35.42) 147.22,35.56 arc(147.41,35.84) 147.47,36.17 147.47,76.04 arc(147.25,77.17) 146.61,78.13 arc(145.92,79.15) 145.68,80.36 145.68,82.96 arc(145.69,83) 145.71,83.03 v1(145.98,83.3)
  BOTTOM w0.114: R77.2 146.05,82.38 arc(146.02,82.46) 145.94,82.49 145.78,82.49 arc(145.7,82.53) 145.66,82.61 145.66,82.94 arc(145.67,82.98) 145.7,83.02 v1(145.98,83.3)
PCIE30_RX0N: length 204.7
  TOP w0.152: J38.153 52.6,61.33 arc(52.59,61.26) 52.55,61.21 52.53,61.19 arc(52.49,61.13) 52.48,61.07 52.48,39.53 arc(52.73,38.29) 53.43,37.23 55.92,34.74 arc(57.29,33.83) 58.9,33.51 131.8,33.51 arc(132.12,33.57) 132.38,33.75 132.45,33.82 arc(132.94,34.15) 133.52,34.26 134.2,34.26 arc(134.39,34.3) 134.56,34.41 v1(134.72,34.57) ; v1(146.46,94.29) 146.63,94.12 arc(146.73,93.96) 146.77,93.77 146.77,93.11 146.65,92.99 J17.41
  ART04 w0.127: v1(134.72,34.57) 134.89,34.41 arc(135.05,34.3) 135.25,34.26 arc(135.76,34.05) 135.97,33.54 135.97,31.87 arc(136.17,31.39) 136.65,31.19 154.36,31.19 arc(155.79,31.78) 156.39,33.22 156.39,79.49 arc(155.97,81.61) 154.77,83.4 154.23,83.93 arc(153.44,85.12) 153.16,86.52 153.16,90.73 arc(152.79,91.62) 151.9,91.99 149.86,91.99 arc(149.75,91.95) 149.7,91.83 arc(149.65,91.71) 149.53,91.66 149.35,91.66 arc(149.24,91.71) 149.19,91.83 arc(149.14,91.95) 149.02,91.99 148.85,91.99 arc(148.73,91.95) 148.68,91.83 arc(148.63,91.71) 148.52,91.66 148.34,91.66 arc(148.22,91.71) 148.17,91.83 arc(148.13,91.95) 148.01,91.99 147.41,91.99 arc(146.96,92.18) 146.77,92.63 146.77,93.76 arc(146.73,93.96) 146.62,94.12 v1(146.46,94.29)
PCIE30_RX0P: length 204.8
  TOP w0.152: v1(147.34,94.29) 147.17,94.12 arc(147.07,93.96) 147.03,93.77 147.03,93.11 147.15,92.99 J17.43 ; J38.151 52.1,61.33 arc(52.11,61.26) 52.15,61.21 52.17,61.19 arc(52.21,61.13) 52.22,61.07 52.22,39.53 arc(52.49,38.19) 53.25,37.05 55.74,34.56 arc(57.19,33.59) 58.9,33.25 131.8,33.25 arc(132.21,33.33) 132.57,33.57 132.63,33.63 arc(133.04,33.91) 133.52,34 134.2,34 arc(134.39,33.96) 134.56,33.86 v1(134.72,33.69)
  ART04 w0.127: v1(147.34,94.29) 147.18,94.12 arc(147.07,93.96) 147.03,93.76 147.03,92.63 arc(147.14,92.36) 147.41,92.25 151.9,92.25 arc(152.97,91.8) 153.42,90.73 153.42,86.52 arc(153.68,85.22) 154.41,84.11 154.95,83.58 arc(156.2,81.7) 156.64,79.49 156.64,33.22 arc(155.97,31.6) 154.36,30.93 136.65,30.93 arc(135.99,31.21) 135.71,31.87 135.71,33.54 arc(135.58,33.87) 135.25,34 arc(135.05,33.97) 134.89,33.86 v1(134.72,33.69)
PCIE30_RX1N: length 204.8
  TOP w0.152: J17.29 143.65,92.99 143.77,93.11 143.77,93.77 arc(143.73,93.96) 143.63,94.12 v1(143.46,94.29) ; J38.157 53.6,61.26 53.48,61.14 53.48,39.55 arc(53.65,38.71) 54.12,38 57.03,35.09 arc(57.67,34.66) 58.43,34.51 130.34,34.51 arc(130.95,34.63) 131.47,34.98 131.54,35.05 arc(132.3,35.56) 133.2,35.74 135.45,35.74 arc(135.64,35.78) 135.8,35.88 v1(135.97,36.05)
  ART04 w0.127: v1(135.97,36.05) 136.13,35.88 arc(136.3,35.78) 136.49,35.74 136.8,35.74 arc(137.23,35.56) 137.41,35.12 137.41,32.53 arc(137.56,32.17) 137.92,32.03 151.3,32.03 arc(151.7,32.19) 151.87,32.59 151.87,83.88 arc(151.81,84.15) 151.66,84.37 arc(151.44,84.71) 151.36,85.1 151.36,88.52 arc(151.23,88.82) 150.93,88.95 150.6,88.95 arc(150.38,88.86) 150.29,88.64 150.29,88.34 arc(149.78,87.83) 149.28,88.34 149.28,88.69 arc(149.02,88.95) 148.77,88.69 148.77,88.34 arc(148.26,87.83) 147.75,88.34 147.75,88.69 arc(147.5,88.95) 147.24,88.69 147.24,88.34 arc(146.74,87.83) 146.23,88.34 146.23,88.69 arc(146.15,88.87) 145.97,88.95 144.45,88.95 arc(143.97,89.15) 143.77,89.62 143.77,91.9 arc(143.71,92.05) 143.57,92.11 143.44,92.11 arc(143.29,92.17) 143.23,92.32 143.23,92.41 arc(143.29,92.56) 143.44,92.62 143.57,92.62 arc(143.71,92.68) 143.77,92.82 143.77,93.76 arc(143.73,93.96) 143.62,94.12 v1(143.46,94.29)
PCIE30_RX1P: length 204.9
  TOP w0.152: v1(144.34,94.29) 144.17,94.12 arc(144.07,93.96) 144.03,93.77 144.03,93.11 144.15,92.99 J17.31 ; J38.155 53.1,61.33 arc(53.11,61.26) 53.15,61.21 53.17,61.19 arc(53.21,61.13) 53.22,61.07 53.22,39.55 arc(53.41,38.61) 53.94,37.82 56.85,34.9 arc(57.58,34.42) 58.43,34.25 130.34,34.25 arc(131.05,34.39) 131.65,34.79 131.72,34.87 arc(132.4,35.32) 133.2,35.48 135.45,35.48 arc(135.64,35.44) 135.8,35.33 v1(135.97,35.17)
  ART04 w0.127: v1(144.34,94.29) 144.18,94.12 arc(144.07,93.96) 144.03,93.76 144.03,89.62 arc(144.15,89.32) 144.45,89.2 145.97,89.2 arc(146.33,89.05) 146.48,88.69 146.48,88.34 arc(146.74,88.08) 146.99,88.34 146.99,88.69 arc(147.5,89.2) 148.01,88.69 148.01,88.34 arc(148.26,88.08) 148.51,88.34 148.51,88.69 arc(149.02,89.2) 149.53,88.69 149.53,88.34 arc(149.78,88.08) 150.04,88.34 150.04,88.64 arc(150.2,89.04) 150.6,89.2 150.93,89.2 arc(151.41,89) 151.61,88.52 151.61,85.1 arc(151.67,84.81) 151.84,84.55 arc(152.05,84.24) 152.12,83.88 152.12,32.59 arc(151.88,32.01) 151.3,31.77 137.92,31.77 arc(137.38,31.99) 137.16,32.53 137.16,35.12 arc(137.05,35.38) 136.8,35.48 136.49,35.48 arc(136.3,35.44) 136.13,35.33 v1(135.97,35.17)
PCIE30_TX0N: length 184.6
  TOP w0.152: v1(139.29,33.56) 139.14,33.41 arc(138.99,33.31) 138.82,33.28 138.13,33.28 arc(137.46,33.14) 136.9,32.76 136.37,32.23 arc(135.56,31.7) 134.62,31.51 58.68,31.51 arc(56.5,31.94) 54.66,33.18 52.14,35.7 arc(50.91,37.53) 50.48,39.7 50.48,57.5 arc(50.52,57.58) 50.6,57.62 arc(50.69,57.66) 50.72,57.74 50.72,58.11 arc(50.69,58.19) 50.6,58.23 arc(50.52,58.27) 50.48,58.35 50.48,58.72 arc(50.52,58.8) 50.6,58.84 arc(50.69,58.88) 50.72,58.96 50.72,59.33 arc(50.69,59.41) 50.6,59.45 arc(50.52,59.48) 50.48,59.57 50.48,59.94 arc(50.52,60.02) 50.6,60.06 arc(50.69,60.09) 50.72,60.18 50.72,60.55 arc(50.69,60.63) 50.6,60.67 arc(50.52,60.7) 50.48,60.79 50.48,61.07 arc(50.49,61.13) 50.53,61.19 50.55,61.21 arc(50.59,61.26) 50.6,61.33 J38.145
  ART04 w0.127: v1(147.89,86.78) 148.06,86.62 arc(148.17,86.45) 148.21,86.26 148.21,85.68 arc(148.26,85.43) 148.39,85.23 150.05,83.57 arc(150.66,82.66) 150.88,81.58 150.88,34.22 arc(150.6,33.55) 149.92,33.27 139.77,33.27 arc(139.6,33.31) 139.45,33.41 v1(139.29,33.56)
  BOTTOM w0.152: C125.1 148.05,87.72 arc(148.17,87.54) 148.21,87.34 148.21,87.3 arc(148.17,87.11) 148.06,86.95 v1(147.89,86.78)
PCIE30_TX0P: length 184.6
  TOP w0.152: J38.143 50.1,61.26 50.22,61.14 50.22,39.7 arc(50.67,37.43) 51.95,35.52 54.47,32.99 arc(56.41,31.7) 58.68,31.25 134.62,31.25 arc(135.66,31.46) 136.55,32.05 137.08,32.58 arc(137.56,32.9) 138.13,33.02 138.73,33.02 arc(138.94,32.98) 139.11,32.86 v1(139.29,32.68)
  ART04 w0.127: v1(148.78,86.78) 148.61,86.62 arc(148.5,86.45) 148.46,86.26 148.46,85.68 arc(148.49,85.53) 148.57,85.41 150.23,83.75 arc(150.9,82.75) 151.13,81.58 151.13,34.22 arc(150.78,33.37) 149.92,33.02 139.86,33.02 arc(139.65,32.98) 139.47,32.86 v1(139.29,32.68)
  BOTTOM w0.152: C126.1 148.62,87.72 arc(148.51,87.54) 148.47,87.34 148.47,87.3 arc(148.5,87.11) 148.61,86.95 v1(148.78,86.78)
PCIE30_TX1N: length 184.6
  TOP w0.152: J38.149 51.6,61.33 arc(51.59,61.26) 51.55,61.21 51.53,61.19 arc(51.49,61.13) 51.48,61.07 51.48,60.55 arc(51.52,60.46) 51.6,60.43 arc(51.69,60.39) 51.72,60.3 51.72,59.94 arc(51.69,59.85) 51.6,59.82 arc(51.52,59.78) 51.48,59.69 51.48,59.33 arc(51.52,59.24) 51.6,59.21 arc(51.69,59.17) 51.72,59.09 51.72,58.72 arc(51.69,58.63) 51.6,58.6 arc(51.52,58.56) 51.48,58.48 51.48,58.11 arc(51.52,58.02) 51.6,57.99 arc(51.69,57.95) 51.72,57.87 51.72,57.5 arc(51.69,57.41) 51.6,57.38 arc(51.52,57.34) 51.48,57.26 51.48,39.64 arc(51.82,37.91) 52.8,36.45 55.26,33.99 arc(56.9,32.89) 58.83,32.51 133.64,32.51 arc(135.1,32.8) 136.34,33.63 137.1,34.39 arc(137.35,34.56) 137.65,34.62 137.72,34.62 arc(137.9,34.65) 138.05,34.75 v1(138.21,34.91)
  ART04 w0.127: v1(138.21,34.91) 138.37,34.74 arc(138.54,34.63) 138.73,34.59 146.22,34.59 arc(146.93,34.73) 147.53,35.13 147.84,35.45 arc(148.21,35.99) 148.34,36.64 148.34,71.92 arc(148.48,72.28) 148.84,72.43 149.35,72.43 arc(149.61,72.69) 149.35,72.94 148.84,72.94 arc(148.34,73.45) 148.84,73.96 149.35,73.96 arc(149.61,74.21) 149.35,74.46 148.84,74.46 arc(148.34,74.97) 148.84,75.48 149.35,75.48 arc(149.61,75.73) 149.35,75.99 148.84,75.99 arc(148.48,76.14) 148.34,76.5 148.34,81.05 arc(148.13,82.08) 147.55,82.95 145.47,85.02 arc(145.34,85.23) 145.29,85.47 145.29,86.26 arc(145.25,86.45) 145.14,86.62 v1(144.97,86.78)
  BOTTOM w0.152: C123.1 145.13,87.72 arc(145.25,87.54) 145.29,87.34 145.29,87.3 arc(145.25,87.11) 145.14,86.95 v1(144.97,86.78)
PCIE30_TX1P: length 184.6
  TOP w0.152: J38.147 51.1,61.33 arc(51.11,61.26) 51.15,61.21 51.17,61.19 arc(51.21,61.13) 51.22,61.07 51.22,39.64 arc(51.58,37.81) 52.62,36.26 55.08,33.8 arc(56.8,32.65) 58.83,32.25 133.64,32.25 arc(135.2,32.56) 136.52,33.44 137.28,34.2 arc(137.45,34.32) 137.65,34.36 137.67,34.36 arc(137.86,34.32) 138.02,34.21 v1(138.21,34.03)
  ART04 w0.127: v1(145.86,86.78) 145.69,86.62 arc(145.58,86.45) 145.54,86.26 145.54,85.47 arc(145.57,85.33) 145.65,85.2 147.73,83.13 arc(148.37,82.17) 148.59,81.05 148.59,76.5 arc(148.66,76.32) 148.84,76.24 149.35,76.24 arc(149.86,75.73) 149.35,75.23 148.84,75.23 arc(148.59,74.97) 148.84,74.72 149.35,74.72 arc(149.86,74.21) 149.35,73.7 148.84,73.7 arc(148.59,73.45) 148.84,73.19 149.35,73.19 arc(149.86,72.69) 149.35,72.18 148.84,72.18 arc(148.66,72.1) 148.59,71.92 148.59,36.64 arc(148.44,35.9) 148.02,35.27 147.71,34.95 arc(147.03,34.5) 146.22,34.34 138.73,34.34 arc(138.53,34.3) 138.37,34.19 v1(138.21,34.03)
  BOTTOM w0.152: C124.1 145.7,87.72 arc(145.58,87.54) 145.54,87.34 145.54,87.3 arc(145.58,87.11) 145.69,86.95 v1(145.86,86.78)
PCIE30X2_CLKREQN_M1: length 123.8
  TOP w0.173: v1(132.45,72.1) 133.41,73.07 133.41,79.59 135.44,81.62 135.44,85.18 138.68,88.41 148.16,88.41 149.27,87.3 149.27,86.34 149.4,86.21 J17.52 ; v1(55.1,58.91) 54.6,59.41 J38.161
  BOTTOM w0.173: v1(132.45,72.1) 131.16,72.1 130.94,72.32 130.94,74.48 130.34,75.08 125.04,75.08 123.85,73.88 108.51,73.88 105.23,70.6 73.42,70.6 65.17,62.35 57.18,62.35 56.44,61.62 56.44,60.24 v1(55.1,58.91)
PCIE30X2_PERSTN_M1: length 121.6
  TOP w0.173: J38.165 55.6,60.41 v1(55.1,59.91) ; v1(133.45,72.1) 133.94,72.59 133.94,79.38 135.97,81.4 135.97,84.9 138.74,87.68 146.81,87.68 147.36,87.13 147.36,86.35 147.6,86.1 148.67,86.1 148.9,85.87 J17.50
  BOTTOM w0.173: v1(133.45,72.1) 132.93,72.62 132.36,72.62 131.95,73.02 131.95,75.3 131.61,75.64 124.75,75.64 123.55,74.45 108.34,74.45 104.99,71.1 73.18,71.1 64.97,62.89 56.87,62.89 55.85,61.87 55.85,60.66 v1(55.1,59.91)
PCIE30X2_WAKEN_M1: length 123.3
  TOP w0.173: J38.163 v1(55.1,60.91) ; J17.54 149.9,85.79 150.32,86.2 150.32,87.55 148.84,89.02 136.4,89.02 134.92,87.55 134.92,81.83 132.89,79.8 132.89,73.67 v1(132.45,73.23)
  BOTTOM w0.173: v1(55.1,60.91) 55.1,61.98 56.41,63.29 64.64,63.29 72.77,71.42 104.85,71.42 108.2,74.77 123.42,74.77 124.61,75.97 131.88,75.97 132.45,75.4 v1(132.45,73.23)
PDN: length 6.5
  TOP w0.173: U21.7 142.7,75.27 143.08,74.89 v1(143.08,71.67)
  BOTTOM w0.173: R84.2 v1(143.08,71.67)
PE_TXN: length 4.3
  TOP w0.152: J35.31 113.5,75.38 113.2,75.08 113.2,73.7 v1(113.53,73.37)
  BOTTOM w0.152: v1(113.53,73.37) 113.59,73.32 C53.2
PE_TXP: length 4.3
  TOP w0.152: v1(112.64,73.37) 112.95,73.68 112.95,75.06 112.7,75.31 J35.33
  BOTTOM w0.152: v1(112.64,73.37) 112.57,73.31 C54.2
PETN0: length 3.3
  TOP w0.152: v1(147.96,89.83) 148.27,90.14 148.27,90.94 148.15,91.06 J17.47
  BOTTOM w0.152: v1(147.96,89.83) 147.83,89.7 C125.2
PETN1: length 3.3
  TOP w0.152: J17.35 145.15,91.06 145.27,90.94 145.27,90.14 v1(144.96,89.83)
  BOTTOM w0.152: C123.2 144.91,89.78 v1(144.96,89.83)
PETP0: length 3.3
  TOP w0.152: J17.49 148.65,91.06 148.53,90.94 148.53,90.14 v1(148.84,89.83)
  BOTTOM w0.152: v1(148.84,89.83) 148.84,89.83 C126.2
PETP1: length 3.3
  TOP w0.152: J17.37 145.65,91.06 145.53,90.94 145.53,90.14 v1(145.84,89.83)
  BOTTOM w0.152: v1(145.84,89.83) 145.92,89.75 C124.2
PHY0_CLKOUT125: length 3
  TOP w0.173: R105.2 72.6,48.36 U18.35
PHY0_LED1: length 63.6
  TOP w0.173: U18.33 70.91,47.56 72.09,46.38 v1(72.09,46.15) R108.1
  ART04 w0.16: v1(72.09,46.15) 71.65,46.58 65.1,46.58 64.08,47.6 64.08,52.42 63.09,53.42 63.09,71.15 61.75,72.49 61.75,82.9 60.1,84.55 60.1,93.06 J11.14
PHY0_LED2: length 72
  TOP w0.173: R109.1 v1(72.09,47.16) 71.29,47.96 U18.34
  ART04 w0.16: J11.12 72.54,94.79 62.48,94.79 60.47,92.78 60.47,84.97 62.36,83.08 62.36,72.77 64.11,71.01 64.11,57.48 63.78,57.14 63.78,53.62 64.8,52.6 64.8,48.71 65.46,48.05 71.2,48.05 v1(72.09,47.16)
PHY1_CLKOUT125: length 3
  TOP w0.173: U19.35 93.05,48.36 R134.2
PHY1_LED1: length 68.3
  TOP w0.173: U19.33 91.35,47.56 92.53,46.38 v1(92.53,46.15) R137.1
  ART04 w0.16: J18.14 82.71,94.59 90.46,94.59 90.78,94.27 90.78,87.06 91.89,85.95 95.25,85.95 95.71,85.49 95.71,81.18 94.09,79.55 94.09,59.95 93.57,59.43 93.57,48.07 93.25,47.75 92.37,47.75 92.05,47.43 92.05,46.63 v1(92.53,46.15)
PHY1_LED2: length 59.3
  TOP w0.173: U19.34 91.74,47.96 v1(92.53,47.16) R138.1
  ART04 w0.16: v1(92.53,47.16) 93.66,47.16 93.98,47.48 93.98,58.95 95.09,60.06 95.09,61.65 94.52,62.22 94.52,79.38 96.71,81.57 96.71,85.61 95.78,86.54 92.32,86.54 91.62,87.25 91.62,95.61 J18.12
PWM3_IR: length 184.5
  TOP w0.173: J38.189 63.1,60.41 v1(63.6,59.91)
  ART03 w0.16: v1(63.6,59.91) 63.11,60.39 63.11,61.74 62.79,62.06 31.92,62.06 31.45,62.52 31.45,71.91 32.66,73.12 32.66,79.18 34.18,80.69 50.06,80.69 50.95,81.58 50.95,95.97 51.27,96.29 56.79,96.29 58.27,97.76 100.05,97.76 101.27,96.55 109.37,96.55 110.08,95.83 v1(145.54,95.83)
  BOTTOM w0.173: R34.1 v1(145.54,95.83)
RECOVERY_KEY: length 69.9
  TOP w0.173: J38.60 29.35,66.56 29,66.21 21.36,66.21 v1(20.84,66.74)
  ART03 w0.16: v1(20.84,66.74) 21.46,66.11 21.46,14.86 20.5,13.89 17.98,13.89 v1(17.68,14.19)
  BOTTOM w0.173: v1(17.68,14.19) 17.69,14.19 R26.2
REF_CLKN: length 15.2
  TOP w0.114: R111.2 142.75,82.4 arc(142.78,82.49) 142.86,82.52 143.02,82.52 arc(143.1,82.55) 143.14,82.63 143.14,82.98 v1(142.81,83.3)
  BOTTOM w0.114: C127.1 150.11,87.49 arc(150.15,87.41) 150.23,87.37 150.39,87.37 arc(150.47,87.34) 150.5,87.26 150.5,85.49 arc(150.48,85.37) 150.4,85.26 150.24,85.09 arc(150.13,85.02) 150,85 143.89,85 arc(143.67,84.95) 143.48,84.83 143.3,84.65 arc(143.18,84.46) 143.14,84.24 143.14,83.85 arc(143.1,83.64) 142.98,83.47 v1(142.81,83.3) 142.98,83.13 arc(143.1,82.96) 143.14,82.76 143.14,82.58 arc(143.09,82.36) 142.97,82.17 R111.2
REF_CLKP: length 15.2
  TOP w0.114: R87.2 143.76,82.4 arc(143.73,82.49) 143.65,82.52 143.49,82.52 arc(143.41,82.55) 143.38,82.63 143.38,82.98 v1(143.7,83.3)
  BOTTOM w0.114: R87.2 143.54,82.17 arc(143.42,82.36) 143.38,82.58 143.38,82.76 arc(143.42,82.96) 143.53,83.13 v1(143.7,83.3) 143.53,83.47 arc(143.42,83.64) 143.38,83.85 143.38,84.24 arc(143.4,84.37) 143.47,84.48 143.65,84.66 arc(143.76,84.73) 143.89,84.76 150,84.76 arc(150.22,84.8) 150.41,84.92 150.58,85.09 arc(150.7,85.28) 150.74,85.49 150.74,87.26 arc(150.78,87.34) 150.86,87.37 151.02,87.37 arc(151.1,87.41) 151.13,87.49 C128.1
REFCLKN: length 4.1
  TOP w0.114: v1(150.18,89.85) 150.5,90.18 150.5,90.34 150.39,90.45 150.03,90.45 149.78,90.71 149.78,90.97 149.65,91.1 J17.53
  BOTTOM w0.114: C127.2 150.5,89.33 150.5,89.53 v1(150.18,89.85)
REFCLKP: length 4.1
  TOP w0.114: v1(151.07,89.85) 150.74,90.18 150.74,90.44 150.49,90.69 150.13,90.69 150.02,90.81 150.02,90.97 150.15,91.1 J17.55
  BOTTOM w0.114: v1(151.07,89.85) 150.74,89.53 150.74,89.33 C128.2
RESET_KEY: length 68
  TOP w0.173: J38.29 21.6,38.39 20.29,37.08 20.29,30.65 23.52,27.43 23.52,14.09 22.79,13.37 17.39,13.37 16.87,13.89 11.6,13.89 v1(11.07,13.37)
  BOTTOM w0.173: v1(11.07,13.37) 11.06,13.38 C63.1 10.15,12.54 D1.2 10.71,10.3 SW1.2
RS232_3V3: length 6.1
  TOP w0.305: U11.16 64.52,24.42 64.52,22.96 64.21,22.65 C42.1 62.09,21.18 L7.1
RS232_R1IN: length 11.4
  TOP w0.173: U11.13 v1(68.32,22.91)
  BOTTOM w0.173: J8.4 67.82,14.32 67.82,22.41 v1(68.32,22.91)
RS232_R1OUT: length 30.4
  TOP w0.173: J13.1 80.31,6.78 80.14,6.95 80.14,15.7 79.79,16.05 74.89,16.05 74.55,16.39 74.55,20.5 74.2,20.85 69.97,20.85 69.6,21.22 U11.12
RS232_R2IN: length 9.9
  TOP w0.173: J8.1 78.49,14.69 78.14,15.03 73.84,15.03 73.4,15.47 U11.8
RS232_R2OUT: length 19.9
  TOP w0.173: J14.1 82.17,13.89 82.17,17.6 81.51,18.26 76.85,18.26 76.5,18.6 76.5,22.53 76.12,22.91 73.75,22.91 73.4,23.25 U11.9
RS232_T1IN: length 26.2
  TOP w0.173: J13.2 81.47,9.32 81.13,9.66 81.13,16.62 80.68,17.06 75.91,17.06 75.56,17.41 75.56,21.18 74.89,21.85 71.4,21.85 70.86,22.39 U11.11
RS232_T1OUT: length 17.7
  TOP w0.173: U11.14 67.06,21.88 66.69,21.51 63.8,21.51 63.5,21.21 63.5,19.73 63.25,19.48 59.82,19.48 59.44,19.1 J8.6
RS232_T2IN: length 23
  TOP w0.173: U11.10 72.14,26.01 72.49,26.36 74.38,26.36 74.73,26.01 74.73,24.24 75.07,23.9 77.15,23.9 77.6,23.45 77.6,19.98 77.85,19.73 v1(80.09,19.73)
  BOTTOM w0.173: v1(80.09,19.73) 80.09,15.63 80.43,15.29 83.31,15.29
RS232_T2OUT: length 5.8
  TOP w0.173: U11.7 72.14,14.83 J8.3
RS485_1_3V3: length 10.5
  TOP w0.305: D4.1 v1(48.26,19.6) L5.2 ; U8.8 v1(53.98,20.49)
  BOTTOM w0.305: v1(53.98,20.49) C39.1 53.97,19.6 v1(48.26,19.6)
RS485_1_A: length 8.4
  TOP w0.305: R38.2 51.82,16.57 51.82,13.86 51.51,13.56 J10.2 ; R38.2 R37.1 ; R38.2 51.82,17.06 51.82,17.83 51.44,18.21 U8.6
RS485_1_B: length 8.7
  TOP w0.305: R38.1 52.27,16.51 52.27,13.86 52.58,13.56 J10.1 ; R38.1 52.27,17.11 52.27,17.78 52.7,18.21 U8.7 ; R38.1 R41.1
RS485_1_DIR: length 69
  TOP w0.173: v1(52.7,27.61) 48.51,27.61 47.54,28.57 v1(47.54,53.45) ; v1(72.1,59.91) 71.6,60.41 J38.223 ; U8.3 51.44,23.08 51.61,22.91 52.53,22.91 52.7,23.08 U8.2 v1(52.7,25.89)
  BOTTOM w0.173: v1(52.7,27.61) v1(52.7,25.89) R40.1 ; v1(47.54,53.45) 48.54,54.45 67.58,54.45 68.22,55.1 68.22,56.03 72.1,59.9 v1(72.1,59.91)
RS485_2_3V3: length 10.5
  TOP w0.305: D5.1 v1(40.64,19.48) L6.2 ; U13.8 v1(46.35,20.49)
  BOTTOM w0.305: v1(46.35,20.49) C44.1 40.76,19.6 v1(40.64,19.48)
RS485_2_A: length 8.4
  TOP w0.305: R67.1 R68.2 ; R68.2 44.2,16.57 44.2,13.86 43.89,13.56 J10.4 ; R68.2 44.2,17.06 44.2,17.7 43.81,18.08 U13.6
RS485_2_B: length 8.7
  TOP w0.305: U13.7 45.09,18.08 44.65,17.65 44.65,17.11 R68.1 ; R70.1 R68.1 ; R68.1 44.65,16.51 44.65,13.86 44.96,13.56 J10.3
RS485_2_DIR: length 67.1
  TOP w0.173: U13.3 43.81,23.08 43.99,22.91 44.91,22.91 45.09,23.08 U13.2 v1(45.09,25.89) ; v1(47.57,27.63) 47.05,28.16 47.05,53.96 v1(47.54,54.45) ; J38.225 v1(72.1,60.91)
  BOTTOM w0.173: v1(47.57,27.63) 47.57,25.45 47.23,25.1 R69.1 v1(45.09,25.89) ; v1(72.1,60.91) 66.79,55.6 48.68,55.6 v1(47.54,54.45)
RX8010_NIRQ1: length 51.5
  TOP w0.173: v1(20.84,65.74) 21.11,65.47 44.69,65.47 45.1,65.06 J38.123
  ART03 w0.16: v1(20.84,65.74) 20.84,65.73 20.3,65.2 19.58,65.2 19.35,65.42 19.35,68.94 16.64,71.65 v1(16.64,83.71)
  BOTTOM w0.173: v1(16.64,83.71) U17.7 16.64,85.06 R72.2
S0: length 2.4
  TOP w0.173: R86.2 140.59,78.52 U21.2
S1: length 2.3
  TOP w0.173: R85.2 140.23,77.87 U21.3
S2: length 2.1
  TOP w0.173: R143.1 139.86,77.22 U21.4
SARADC_VIN1: length 134.6
  TOP w0.173: J38.56 28.35,67.24 v1(27.85,66.74) ; R55.1 v1(114.29,24.04)
  ART03 w0.16: v1(27.85,66.74) 27.94,66.65 27.94,63.69 26.39,62.14 26.39,31.7 26.8,31.29 v1(26.8,29.66)
  BOTTOM w0.173: v1(26.8,29.66) 58.45,29.66 59.3,28.81 105.86,28.81 108.97,25.7 108.97,23.41 109.47,22.91 113.15,22.91 v1(114.29,24.04)
SARADC_VIN3: length 3.7
  TOP w0.173: J38.58 v1(28.85,68.74)
  BOTTOM w0.173: R219.2 R220.1 28.83,68.76 v1(28.85,68.74)
SARADC_VIN4: length 132.6
  TOP w0.173: R56.1 v1(112.76,24.04) ; J38.52 27.35,68.24 v1(27.85,67.74)
  ART03 w0.16: v1(27.85,67.74) 27.34,67.23 27.34,63.93 25.79,62.38 25.79,31.57 v1(25.83,31.53)
  BOTTOM w0.173: v1(112.76,24.04) 112.24,23.52 110.73,23.52 110.36,23.89 110.36,26.33 105.91,30.78 26.58,30.78 v1(25.83,31.53)
SARADC_VIN5: length 129
  TOP w0.173: R58.1 v1(111.24,24.04) ; J38.54 v1(27.85,68.74)
  ART03 w0.16: v1(27.85,68.74) 28.45,68.14 28.45,63.48 26.9,61.92 26.9,31.92 v1(27.29,31.53)
  BOTTOM w0.173: v1(111.24,24.04) 111.24,26.19 106.13,31.3 27.51,31.3 v1(27.29,31.53)
SARADC_VIN6: length 129.4
  TOP w0.173: R59.1 v1(109.71,24.04) ; v1(26.85,67.74) 26.35,68.24 J38.48
  ART03 w0.16: v1(25.83,30.53) 25.29,31.07 25.29,62.59 25.76,63.06 26.84,64.14 26.84,67.15 26.84,67.16 26.84,67.72 v1(26.85,67.74)
  BOTTOM w0.173: v1(25.83,30.53) 26.14,30.22 105.46,30.22 109.71,25.97 v1(109.71,24.04)
SARADC_VIN7: length 128.9
  TOP w0.173: J38.50 v1(26.85,68.74) ; R71.1 v1(108.19,24.04)
  ART03 w0.16: v1(24.83,29.66) 24.78,29.71 24.78,62.8 25.4,63.42 26.33,64.35 26.33,68.22 v1(26.85,68.74)
  BOTTOM w0.173: v1(108.19,24.04) 108.19,25.59 105.49,28.29 58.93,28.29 58.09,29.13 25.36,29.13 v1(24.83,29.66)
SATA0_RXN: length 144
  TOP w0.114: v1(119.25,35.42) 119.08,35.59 arc(118.91,35.71) 118.71,35.75 58.77,35.75 arc(58.05,35.89) 57.44,36.3 55.14,38.6 arc(54.75,39.19) 54.61,39.88 54.61,56.83 arc(54.65,57.05) 54.78,57.24 56.01,58.47 arc(56.08,58.57) 56.1,58.7 56.1,63.53 arc(56.02,63.73) 55.82,63.81 46.72,63.81 arc(46.07,64.08) 45.81,64.72 45.81,65.58 arc(45.66,65.95) 45.29,66.1 42.45,66.1 arc(41.76,66.38) 41.48,67.07 41.48,68.99 arc(41.46,69.06) 41.42,69.13 41.41,69.14 arc(41.36,69.21) 41.35,69.28 J38.108
  ART03 w0.102: v1(125.28,12.39) 125.44,12.55 arc(125.55,12.71) 125.59,12.91 125.59,13.72 arc(125.57,13.81) 125.52,13.88 125.38,14.03 arc(125.3,14.08) 125.21,14.09 119.53,14.09 arc(119.11,14.18) 118.76,14.41 arc(118.52,14.76) 118.44,15.18 118.44,31.57 arc(118.68,32.77) 119.35,33.78 120.01,34.43 arc(120.05,34.5) 120.07,34.57 120.07,35.5 arc(120.01,35.64) 119.86,35.7 119.72,35.7 arc(119.55,35.67) 119.4,35.57 v1(119.25,35.42)
  BOTTOM w0.114: v1(125.28,12.39) 125.48,12.2 arc(125.59,12.03) 125.63,11.82 125.63,11.8 arc(125.59,11.59) 125.48,11.42 C62.1
SATA0_RXP: length 144.1
  TOP w0.114: J38.110 41.85,69.28 arc(41.84,69.21) 41.79,69.14 41.78,69.13 arc(41.74,69.06) 41.72,68.99 41.72,67.07 arc(41.93,66.55) 42.45,66.34 45.29,66.34 arc(45.83,66.12) 46.05,65.58 46.05,64.72 arc(46.25,64.25) 46.72,64.05 55.82,64.05 arc(56.19,63.9) 56.34,63.53 56.34,58.7 arc(56.3,58.48) 56.18,58.3 54.95,57.07 arc(54.88,56.96) 54.85,56.83 54.85,39.88 arc(54.97,39.28) 55.31,38.77 57.61,36.47 arc(58.14,36.11) 58.77,35.99 118.71,35.99 arc(118.91,36.03) 119.08,36.14 v1(119.25,36.31)
  ART03 w0.102: v1(126.18,12.39) 126.02,12.55 arc(125.91,12.71) 125.87,12.91 125.87,13.72 arc(125.83,13.91) 125.72,14.08 125.57,14.22 arc(125.41,14.33) 125.21,14.37 119.53,14.37 arc(119.22,14.43) 118.96,14.61 arc(118.78,14.87) 118.72,15.18 118.72,31.57 arc(118.94,32.66) 119.55,33.58 120.2,34.23 arc(120.31,34.39) 120.35,34.57 120.35,35.5 arc(120.2,35.84) 119.86,35.98 119.79,35.98 arc(119.6,36.02) 119.44,36.13 v1(119.25,36.31)
  BOTTOM w0.114: v1(126.18,12.39) 126.02,12.24 arc(125.91,12.08) 125.88,11.89 125.88,11.85 arc(125.92,11.64) 126.03,11.47 C211.1
SATA0_TXN: length 144
  TOP w0.114: J38.112 42.35,69.28 arc(42.36,69.21) 42.41,69.14 42.42,69.13 arc(42.46,69.06) 42.48,68.99 42.48,67.67 arc(42.73,67.07) 43.32,66.82 46.04,66.82 arc(46.47,66.65) 46.65,66.22 46.65,65.45 arc(46.91,64.81) 47.54,64.55 55.97,64.55 arc(56.29,64.49) 56.56,64.31 arc(56.74,64.04) 56.8,63.72 56.8,57.33 arc(56.78,57.2) 56.71,57.1 55.81,56.19 arc(55.68,56.01) 55.64,55.79 55.64,40.81 arc(55.8,40.02) 56.25,39.35 57.65,37.94 arc(58.64,37.28) 59.8,37.05 117.58,37.05 arc(117.78,37.01) 117.96,36.89 v1(118.14,36.72)
  ART03 w0.102: v1(118.14,36.72) 117.98,36.88 arc(117.81,36.99) 117.62,37.02 117.54,37.02 arc(117.4,36.96) 117.34,36.82 117.34,34.54 arc(117.18,34.16) 116.81,34.01 116.43,34.01 arc(116.18,33.75) 116.43,33.5 116.81,33.5 arc(117.34,32.96) 116.81,32.43 116.43,32.43 arc(116.18,32.18) 116.43,31.92 116.81,31.92 arc(117.18,31.77) 117.34,31.39 117.34,22.76 arc(117.18,22.38) 116.81,22.23 116.76,22.23 arc(116.51,21.97) 116.76,21.72 116.81,21.72 arc(117.34,21.18) 116.81,20.65 116.71,20.65 arc(116.57,20.59) 116.51,20.45 116.51,20.4 arc(116.58,20.22) 116.76,20.14 116.81,20.14 arc(117.18,19.99) 117.34,19.61 117.34,13.98 arc(117.39,13.72) 117.54,13.5 arc(117.76,13.36) 118.02,13.31 121.7,13.31 arc(121.97,13.19) 122.09,12.92 122.09,12.91 arc(122.12,12.71) 122.23,12.55 v1(122.39,12.39)
  BOTTOM w0.114: v1(122.39,12.39) 122.23,12.24 arc(122.13,12.08) 122.09,11.89 122.09,11.85 arc(122.13,11.64) 122.25,11.47 C61.1
SATA0_TXP: length 144
  TOP w0.114: J38.114 42.85,69.28 arc(42.84,69.21) 42.79,69.14 42.78,69.13 arc(42.74,69.06) 42.72,68.99 42.72,67.67 arc(42.9,67.24) 43.32,67.06 46.04,67.06 arc(46.64,66.82) 46.89,66.22 46.89,65.45 arc(47.08,64.98) 47.54,64.79 55.97,64.79 arc(56.38,64.71) 56.73,64.48 arc(56.96,64.13) 57.04,63.72 57.04,57.33 arc(57,57.11) 56.88,56.92 55.98,56.02 arc(55.91,55.92) 55.88,55.79 55.88,40.81 arc(56.02,40.11) 56.42,39.52 57.82,38.11 arc(58.73,37.51) 59.8,37.29 117.61,37.29 arc(117.8,37.33) 117.97,37.44 v1(118.14,37.61)
  ART03 w0.102: v1(121.5,12.39) 121.7,12.59 arc(121.78,12.71) 121.81,12.85 121.81,12.92 arc(121.78,13) 121.7,13.03 118.02,13.03 arc(117.65,13.1) 117.34,13.31 arc(117.13,13.62) 117.06,13.98 117.06,19.61 arc(116.99,19.79) 116.81,19.86 116.76,19.86 arc(116.39,20.02) 116.23,20.4 116.23,20.45 arc(116.37,20.79) 116.71,20.93 116.81,20.93 arc(117.06,21.18) 116.81,21.44 116.76,21.44 arc(116.23,21.97) 116.76,22.5 116.81,22.5 arc(116.99,22.58) 117.06,22.76 117.06,31.39 arc(116.99,31.57) 116.81,31.64 116.43,31.64 arc(115.9,32.18) 116.43,32.71 116.81,32.71 arc(117.06,32.96) 116.81,33.22 116.43,33.22 arc(115.9,33.75) 116.43,34.29 116.81,34.29 arc(116.99,34.36) 117.06,34.54 117.06,36.82 arc(117.2,37.16) 117.54,37.3 117.62,37.3 arc(117.81,37.34) 117.98,37.45 v1(118.14,37.61)
  BOTTOM w0.114: v1(121.5,12.39) 121.69,12.2 arc(121.81,12.03) 121.85,11.82 121.85,11.8 arc(121.81,11.59) 121.69,11.42 C60.1
SATA0RXN: length 3.1
  BOTTOM w0.114: C62.2 125.5,9.99 arc(125.62,9.81) 125.66,9.59 125.66,8.2 arc(125.62,7.98) 125.5,7.8 J34.5
SATA0RXP: length 3.1
  BOTTOM w0.114: C211.2 126.07,10 arc(125.95,9.81) 125.91,9.6 125.91,8.2 arc(125.95,7.98) 126.07,7.8 J34.6
